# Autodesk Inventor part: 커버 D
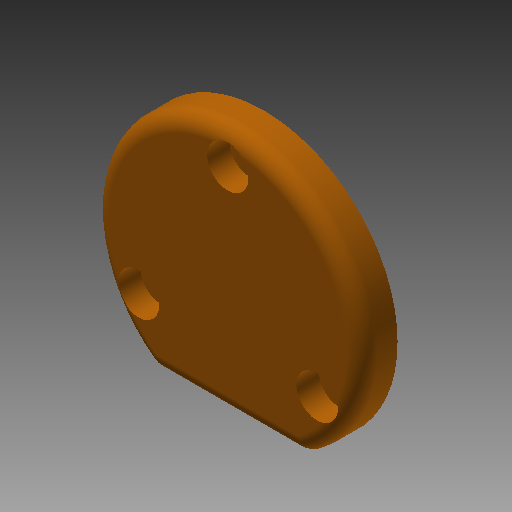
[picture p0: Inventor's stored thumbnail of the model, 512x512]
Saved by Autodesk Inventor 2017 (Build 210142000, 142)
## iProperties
Created: 2020-04
Part Number: 커버 D
Material: 알루미늄 6061
Document SubType Name: Modeling
Designer: mduedu
Density: 2.71 g/cm^3
Mass: 32.8423 g
Surface Area: 61.5912 cm^2
Volume: 12.1189 cm^3
Appearance: 주황색
Author: mduedu
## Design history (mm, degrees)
sketch "스케치1"
  geometry: C1 r 26 at (0, 0); 1 further point
  constraints: 1 centre point, 1 coincident
  dimensions: "d0" = 52 diameter of C1
extrude "돌출1" new body sketch "스케치1" distance "d1" = 7; taper "d2" = 0 deg
sketch "스케치2"
  geometry: L1 (-14.62, -21.5)-(14.62, -21.5); A1 r 26 centre (0, 0) between (-14.62, -21.5) and (14.62, -21.5) reference; 1 further point
  constraints: 2 end point, 2 point on circle, 1 horizontal
  dimensions: "d3" = 21.5 distance from line of L1 point (0, 0)
extrude "돌출2" cut sketch "스케치2" stored distance "d4" = 7; taper "d5" = 0 deg
fillet "모깎기1" dims "d6" = 3
fillet "모깎기2" dims "d7" = 3
sketch "스케치3" dims "d8" = 40
  geometry: 3 further points
  constraints: 2 vertical alignment, 1 coincident, 2 other
hole "구멍1" sketch "스케치3" at (0, 20) diameter "d9" = 4.5; stored, may be unused: countersink angle "d13" = 90 deg, drill point angle "d15" = 118 deg; dims "d10" = 6, "d11" = 8, "d12" = 4.4, "d14" = 8
sketch "스케치4"
  geometry: C1 r 14 at (0, 0); 1 further point
  constraints: 1 centre point, 1 coincident
  dimensions: "d19" = 28 diameter of C1
extrude "돌출3" join sketch "스케치4" distance "d20" = 4; taper "d21" = 0 deg
sketch "스케치5"
  geometry: C1 r 12 at (0, 0); 1 further point
  constraints: 1 centre point, 1 coincident
  dimensions: "d22" = 24 diameter of C1
extrude "돌출4" cut sketch "스케치5" distance "d23" = 8; taper "d24" = 0 deg
fillet "모깎기3" dims "d25" = 3
chamfer "모따기1" distance "d26" = 0.5; stored, may be unused: second distance "d27" = 2, angle "d28" = 45 deg
node "솔리드1"
pattern_circular "원형 패턴1" dims angle "d17" = 360 deg
node "투영된 루프1"
